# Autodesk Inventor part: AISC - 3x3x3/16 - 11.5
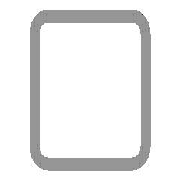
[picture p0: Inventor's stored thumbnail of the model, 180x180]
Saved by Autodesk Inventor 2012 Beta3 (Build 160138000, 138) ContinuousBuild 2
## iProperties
IsCustomPart: 1
Created: 2010-11
Part Number: AISC - 3x3x3/16 - 11.5
Material: Steel, Mild
Description: Tube
Document SubType Name: Modeling
Standard: ANSI
Designer: Beta-8540w
Standards Organization: ANSI
Language: en-US
Size Designation: 3x3x3/16
Categories: <MemberInstance><Categories><Category DisplayName="Structural Shapes" InternalName="089c4875-fa83-4c05-b084-43b9cc11f5ed" Mnemonic="GRDR"><CategoryParameter Dis
Stock Number: 3x3x3/16
Density: 7.86 g/cm^3
_CCFamilyMember: 9
_CCFamilyDisplayName: ANSI AISC (Square) - Tube
_FrameMemberDoc: Frame Member File
_Version: 15.0.0
_GetPNFromCC: 1
G_L: 11.500 in
G_W: 3.000 in
G_H: 3.000 in
Author: Beta-8540w
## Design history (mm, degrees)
node "Start plane"
node "End plane"
sketch "Sketch"
  geometry: L1 (-38.1, -28.575)-(-38.1, 28.575); L2 (-28.575, 38.1)-(28.575, 38.1); L3 (38.1, 28.575)-(38.1, -28.575); L4 (28.575, -38.1)-(-28.575, -38.1); L5 (-28.575, 33.337)-(28.575, 33.338); L6 (33.338, 28.575)-(33.338, -28.575); L7 (28.575, -33.337)-(-28.575, -33.338); L8 (-33.338, -28.575)-(-33.338, 28.575); L9 (0, 56.102)-(0, -56.102) reference; L10 (-56.102, 0)-(56.102, 0) reference; A1 r 9.525 centre (-28.575, -28.575) between (-38.1, -28.575) and (-28.575, -38.1); A2 r 9.525 centre (-28.575, 28.575) between (-28.575, 38.1) and (-38.1, 28.575); A3 r 9.525 centre (28.575, 28.575) between (38.1, 28.575) and (28.575, 38.1); A4 r 9.525 centre (28.575, -28.575) between (28.575, -38.1) and (38.1, -28.575); A5 r 4.763 centre (-28.575, 28.575) between (-28.575, 33.337) and (-33.338, 28.575); A6 r 4.763 centre (28.575, 28.575) between (33.338, 28.575) and (28.575, 33.338); A7 r 4.763 centre (28.575, -28.575) between (28.575, -33.337) and (33.338, -28.575); A8 r 4.763 centre (-28.575, -28.575) between (-33.338, -28.575) and (-28.575, -33.338)
  constraints: 16 end point, 16 point on circle, 8 centre point, 8 tangent, 4 parallel, 3 equal radius, 2 perpendicular, 7 other
  dimensions: "d10" = 76.2 distance between parallel lines of L2 L4 (= G_H); "d11" = 76.2 distance between parallel lines of L1 L3 (= G_W); "d12" = 4.7625 distance between parallel lines of L3 L6 (= G_T); "d15" = 38.1 distance between parallel lines of L2 L10 (= 0.5 x d10); "d16" = 38.1 distance between parallel lines of L9 L3 (= 0.5 x d11); "d17" = 9.525 radius of A1 (= G_IR)
extrude "Body" new body sketch "Sketch" stored distance "d3" = 292.1 (= G_L); taper "d4" = 0 deg
node "Driven Length"
  sketch "Sketch3"
    geometry: L1 (0, 0)-(10, 0) reference
    constraints: 2 end point, 1 horizontal
  workplane "Work Plane3"
  sketch "Sketch4"
    geometry: L1 (-2, 0)-(12, 0) reference; L2 (-2, 292.1)-(12, 292.1) reference
    dimensions: "d19" = 292.1 distance between parallel lines of L1 L2 (derived)
workplane "Work Plane4"
split "Split1"
body "Solid1"
other parameters: "G_W" = 76.2 [user parameter; used in 1 equation term], "G_H" = 76.2 [user parameter; used in 1 equation term], "G_T" = 4.7625 [user parameter; used in 1 equation term], "G_IR" = 9.525 [user parameter; used in 1 equation term], "G_L" = 292.1 (= d19) [user parameter; used in 1 equation term], "G_OFFSET_START" = 0 [user parameter; used in 1 equation term], "G_OFFSET_END" = 38.1 [user parameter; used in 1 equation term], "d13" = 0 (computed from G_OFFSET_START), "d14" = 292.1 (= G_OFFSET_END + B_L), "B_L" = 254 [user parameter; used in 1 equation term], "d18" = 90 deg
